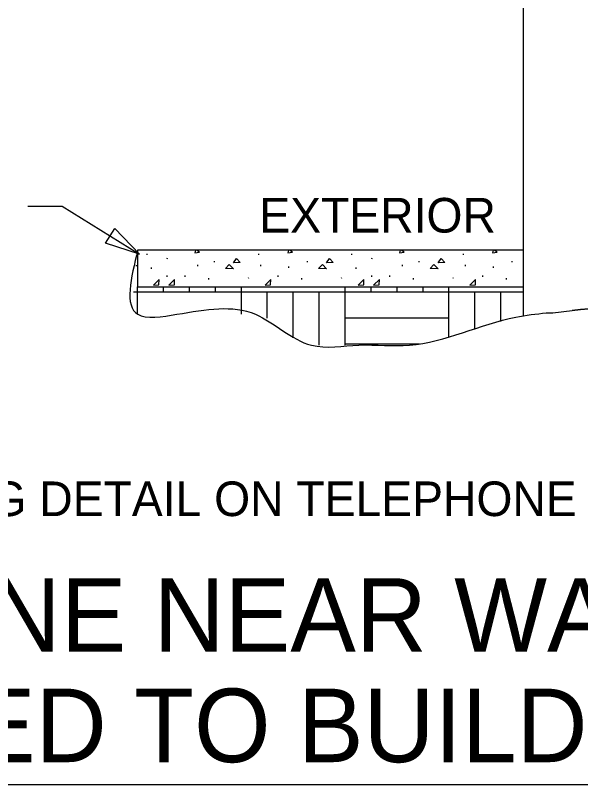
# Model space of a CAD drawing. Extents: x 10099.2 to 10148.4, y 10073.3 to 10116.7.
# Drawn here: x 10124.52 to 10135.41, y 10075.65 to 10090.47 of the extents above; entities that cross this region are included whole.
import ezdxf

# ---------------------------------------------------------------- set-up
doc = ezdxf.new("R2010")
doc.units = 0
for name, color, linetype in [('Level 52', 7, 'Continuous'), ('Level 60', 7, 'Continuous'), ('Level 61', 7, 'Continuous'), ('Level 63', 7, 'Continuous')]:
    doc.layers.add(name, color=color, linetype=linetype)

msp = doc.modelspace()

# ---------------------------------------------------------------- linework, layer by layer
at = {"layer": 'Level 52'}
msp.add_line((10099.233, 10075.654), (10148.423, 10075.654), dxfattribs=at)
at = {"layer": 'Level 60'}
for p, q in [((10134.315, 10085.947), (10126.882, 10085.947)), ((10127.062, 10085.855), (10127.064, 10085.878)), ((10129.212, 10085.855), (10129.217, 10085.878)), ((10131.006, 10085.855), (10131.008, 10085.878)), ((10133.156, 10085.855), (10133.161, 10085.878)), ((10127.448, 10085.776), (10127.453, 10085.799)), ((10128.361, 10085.718), (10128.363, 10085.736)), ((10130.154, 10085.718), (10130.154, 10085.736)), ((10131.392, 10085.776), (10131.397, 10085.799)), ((10132.305, 10085.718), (10132.307, 10085.736)), ((10134.098, 10085.718), (10134.098, 10085.736)), ((10126.878, 10085.642), (10126.848, 10085.642)), ((10127.147, 10085.588), (10127.147, 10085.611)), ((10128.04, 10085.641), (10128.04, 10085.664)), ((10129.254, 10085.641), (10129.254, 10085.664)), ((10129.793, 10085.607), (10129.793, 10085.629)), ((10131.091, 10085.588), (10131.091, 10085.611)), ((10131.984, 10085.641), (10131.984, 10085.664)), ((10133.198, 10085.641), (10133.198, 10085.664)), ((10133.737, 10085.607), (10133.737, 10085.629)), ((10127.448, 10085.434), (10127.448, 10085.455)), ((10127.794, 10085.434), (10127.794, 10085.455)), ((10129.587, 10085.434), (10129.587, 10085.455)), ((10131.392, 10085.434), (10131.392, 10085.455)), ((10131.738, 10085.434), (10131.738, 10085.455)), ((10133.531, 10085.434), (10133.531, 10085.455)), ((10128.25, 10085.384), (10128.25, 10085.407)), ((10129.024, 10085.4), (10129.017, 10085.416)), ((10130.042, 10085.384), (10130.042, 10085.407)), ((10130.816, 10085.4), (10130.808, 10085.416)), ((10132.194, 10085.384), (10132.194, 10085.407)), ((10132.968, 10085.4), (10132.961, 10085.416)), ((10133.986, 10085.384), (10133.986, 10085.407)), ((10126.801, 10085.142), (10134.315, 10085.142)), ((10126.878, 10085.142), (10126.878, 10085.241)), ((10126.878, 10084.72), (10126.878, 10085.142)), ((10126.878, 10085.142), (10128.878, 10085.142)), ((10127.378, 10085.142), (10127.378, 10085.241)), ((10127.878, 10085.142), (10127.878, 10085.241)), ((10128.378, 10085.142), (10128.378, 10085.241)), ((10128.878, 10085.142), (10128.878, 10085.241)), ((10128.878, 10084.711), (10128.878, 10085.142)), ((10129.378, 10084.635), (10129.378, 10085.142)), ((10129.878, 10084.261), (10129.878, 10085.142)), ((10130.378, 10084.117), (10130.378, 10085.142)), ((10130.878, 10085.142), (10130.878, 10085.241)), ((10130.878, 10084.117), (10130.878, 10085.142)), ((10130.878, 10085.142), (10132.878, 10085.142)), ((10131.378, 10085.142), (10131.378, 10085.241)), ((10131.878, 10085.142), (10131.878, 10085.241)), ((10132.378, 10085.142), (10132.378, 10085.241)), ((10132.878, 10085.142), (10132.878, 10085.241)), ((10132.878, 10084.263), (10132.878, 10085.142)), ((10133.378, 10084.427), (10133.378, 10085.142)), ((10133.878, 10084.573), (10133.878, 10085.142)), ((10134.748, 10084.738), (10134.878, 10084.738)), ((10134.878, 10084.738), (10135.253, 10084.782)), ((10130.878, 10084.642), (10132.878, 10084.642)), ((10130.878, 10084.142), (10132.313, 10084.142))]:
    msp.add_line(p, q, dxfattribs=at)
for points in [[(10134.315, 10085.947), (10126.879, 10085.947), (10126.879, 10085.237), (10134.315, 10085.237)], [(10128.727, 10085.702), (10128.785, 10085.783), (10128.856, 10085.706)], [(10130.518, 10085.702), (10130.579, 10085.783), (10130.648, 10085.706)], [(10132.671, 10085.702), (10132.73, 10085.783), (10132.8, 10085.706)], [(10128.574, 10085.596), (10128.644, 10085.673), (10128.725, 10085.587)], [(10130.366, 10085.596), (10130.439, 10085.673), (10130.516, 10085.587)], [(10132.518, 10085.596), (10132.588, 10085.673), (10132.669, 10085.587)], [(10127.291, 10085.276), (10127.296, 10085.378), (10127.185, 10085.269)], [(10127.588, 10085.276), (10127.593, 10085.378), (10127.482, 10085.269)], [(10129.442, 10085.276), (10129.448, 10085.378), (10129.337, 10085.269)], [(10131.235, 10085.276), (10131.24, 10085.378), (10131.129, 10085.269)], [(10131.532, 10085.276), (10131.537, 10085.378), (10131.426, 10085.269)], [(10133.386, 10085.276), (10133.392, 10085.378), (10133.281, 10085.269)]]:
    msp.add_lwpolyline(points, close=True, dxfattribs=at)
for points in [[(10127.993, 10085.947), (10127.982, 10085.897), (10128.073, 10085.908), (10128.015, 10085.947)], [(10129.784, 10085.947), (10129.774, 10085.897), (10129.864, 10085.908), (10129.806, 10085.947)], [(10131.937, 10085.947), (10131.926, 10085.897), (10132.017, 10085.908), (10131.959, 10085.947)], [(10133.728, 10085.947), (10133.718, 10085.897), (10133.808, 10085.908), (10133.75, 10085.947)], [(10134.315, 10085.596), (10134.31, 10085.596), (10134.315, 10085.602)]]:
    msp.add_lwpolyline(points, dxfattribs=at)
for points in [[(10126.882, 10085.947), (10126.882, 10084.711), (10127.637, 10084.711), (10129.148, 10084.711), (10130.227, 10084.117), (10131.144, 10084.117), (10132.115, 10084.117), (10134.166, 10084.657), (10134.756, 10084.739)], [(10135.253, 10084.782), (10137.673, 10084.657), (10138.752, 10084.063), (10139.939, 10084.063), (10140.802, 10084.711), (10141.611, 10084.711), (10142.529, 10084.711), (10142.529, 10085.466), (10143.878, 10085.466), (10144.04, 10085.947)]]:
    msp.add_spline(points, degree=3, dxfattribs=at)
at = {"layer": 'Level 61'}
msp.add_line((10134.315, 10084.679), (10134.315, 10095.546), dxfattribs=at)
msp.add_spline([(10144.04, 10085.947), (10143.878, 10085.466), (10142.529, 10085.466), (10142.529, 10084.711), (10141.611, 10084.711), (10140.802, 10084.711), (10139.939, 10084.063), (10138.752, 10084.063), (10137.673, 10084.657), (10135.253, 10084.782)], degree=3, dxfattribs=at)
at = {"layer": 'Level 63'}
for p, q in [((10124.762, 10086.795), (10125.429, 10086.795)), ((10125.429, 10086.795), (10126.917, 10085.87))]:
    msp.add_line(p, q, dxfattribs=at)
msp.add_lwpolyline([(10126.439, 10086.364), (10126.917, 10085.87), (10126.263, 10086.081)], close=True, dxfattribs=at)

# ---------------------------------------------------------------- texts
at = {"layer": 'Level 52'}
for s, p in [('EMERGENCY TELEPHONE NEAR WALKWAY ', (10102.452, 10078.211)), ('SURFACE MOUNTED TO BUILDING', (10107.129, 10076.086))]:
    msp.add_text(s, height=1.41667, dxfattribs=at).set_placement(p)
at = {"layer": 'Level 63'}
for s, height, p in [('EXTERIOR', 0.6667, (10129.224, 10086.285)), ('SEE DETAIL #1675006 FOR DRILLING DETAIL ON TELEPHONE', 0.66667, (10108.882, 10080.825))]:
    msp.add_text(s, height=height, dxfattribs=at).set_placement(p)

doc.saveas('drawing.dxf')
